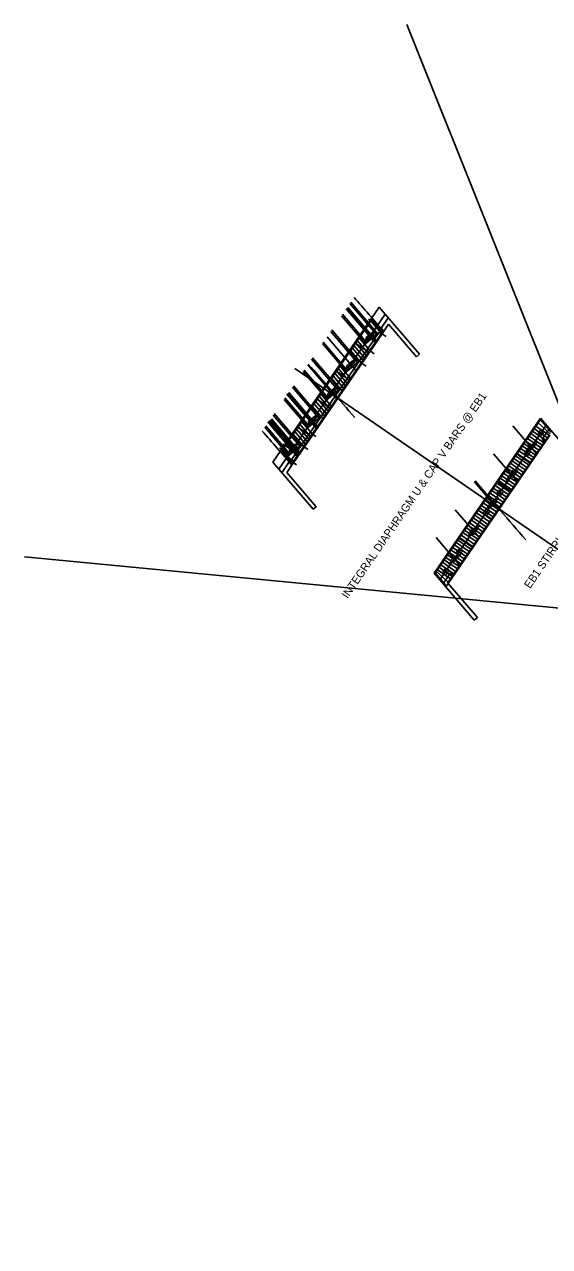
# Model space of a CAD drawing. Extents: x 2378999 to 2381348, y 331302 to 333122.
# Drawn here: x 2378998.8 to 2379130.1, y 331301.9 to 331607.3 of the extents above; entities that cross this region are included whole.
import ezdxf

# ---------------------------------------------------------------- set-up
doc = ezdxf.new("R2010")
doc.units = 0
for name, color, linetype in [('Dimension Lines', 7, 'Continuous'), ('Dimension Lines CELL', 7, 'Continuous'), ('Mis Work Point CELL', 7, 'Continuous'), ('P_SMU_Approach_Slab', 7, 'Continuous'), ('P_SMU_Bent_Cap', 7, 'Continuous'), ('P_SMU_Concrete_Barrier_Rail', 7, 'Continuous'), ('P_SMU_D_Deck_Outline', 7, 'Continuous'), ('P_SMU_Deck', 7, 'Continuous'), ('P_SMU_Girder_Concrete', 7, 'Continuous'), ('P_SMU_Mis_L_Lines', 7, 'Continuous'), ('P_SMU_Mis_Long_Chord', 7, 'Continuous'), ('P_SMU_Mis_Short_Chord', 7, 'Continuous'), ('P_SMU_Rebar_B_Bar', 7, 'Continuous'), ('P_SMU_Rebar_U_Bar', 7, 'Continuous'), ('Plan Sheet CELL', 7, 'Continuous'), ('Rebar Lines', 7, 'Continuous'), ('Scratch_Level_0', 7, 'Continuous'), ('Sup Concrete Slab Lines', 7, 'Continuous'), ('Text', 7, 'Continuous')]:
    doc.layers.add(name, color=color, linetype=linetype)

msp = doc.modelspace()

# ---------------------------------------------------------------- linework, layer by layer
at = {"layer": 'Dimension Lines'}
for p, q in [((2379216.61, 331301.94), (2379094.44, 331607.27)), ((2379085.41, 331533.22), (2379084.81, 331533.63)), ((2379088.1, 331530.07), (2379089.23, 331529.3)), ((2379085.15, 331525.79), (2379086.29, 331525.01)), ((2379083.03, 331522.7), (2379084.27, 331521.85)), ((2379129.98, 331504.63), (2379126.68, 331506.89)), ((2379127.26, 331507.73), (2379130.25, 331505.02)), ((2379127.83, 331508.56), (2379130.52, 331505.42)), ((2379127.86, 331501.54), (2379124.56, 331503.8)), ((2379128.28, 331502.16), (2379124.99, 331504.42)), ((2379128.71, 331502.77), (2379125.41, 331505.04)), ((2379129.13, 331503.39), (2379125.83, 331505.66)), ((2379063.28, 331501.01), (2379062.55, 331501.51)), ((2379126.58, 331499.68), (2379123.29, 331501.95)), ((2379127.01, 331500.3), (2379123.71, 331502.57)), ((2379127.43, 331500.92), (2379124.14, 331503.18)), ((2379065.97, 331497.86), (2379066.87, 331497.24)), ((2379124.04, 331495.97), (2379120.74, 331498.24)), ((2379124.46, 331496.59), (2379121.16, 331498.86)), ((2379124.88, 331497.21), (2379121.59, 331499.48)), ((2379125.31, 331497.83), (2379122.01, 331500.09)), ((2379125.73, 331498.45), (2379122.44, 331500.71)), ((2379121.91, 331492.88), (2379118.61, 331495.15)), ((2379122.34, 331493.5), (2379119.04, 331495.77)), ((2379123.19, 331494.74), (2379119.89, 331497)), ((2379123.61, 331495.36), (2379120.31, 331497.62)), ((2379119.79, 331489.79), (2379116.49, 331492.06)), ((2379120.21, 331490.41), (2379116.92, 331492.68)), ((2379120.64, 331491.03), (2379117.34, 331493.29)), ((2379121.06, 331491.65), (2379117.77, 331493.91)), ((2379121.49, 331492.27), (2379118.19, 331494.53)), ((2379117.66, 331486.7), (2379114.37, 331488.97)), ((2379118.09, 331487.32), (2379114.79, 331489.59)), ((2379118.51, 331487.94), (2379115.22, 331490.2)), ((2379118.94, 331488.56), (2379115.64, 331490.82)), ((2379115.54, 331483.61), (2379112.24, 331485.88)), ((2379116.39, 331484.85), (2379113.09, 331487.11)), ((2379116.82, 331485.47), (2379113.52, 331487.73)), ((2379117.24, 331486.08), (2379113.94, 331488.35)), ((2379113.42, 331480.52), (2379110.12, 331482.79)), ((2379113.84, 331481.14), (2379110.55, 331483.4)), ((2379114.27, 331481.76), (2379110.97, 331484.02)), ((2379114.69, 331482.37), (2379111.39, 331484.64)), ((2379115.12, 331482.99), (2379111.82, 331485.26)), ((2379111.29, 331477.43), (2379108, 331479.69)), ((2379111.72, 331478.05), (2379108.42, 331480.31)), ((2379112.14, 331478.67), (2379108.85, 331480.93)), ((2379112.99, 331479.9), (2379109.7, 331482.17)), ((2379109.6, 331474.96), (2379106.3, 331477.22)), ((2379110.02, 331475.58), (2379106.72, 331477.84)), ((2379110.44, 331476.19), (2379107.15, 331478.46)), ((2379110.87, 331476.81), (2379107.57, 331479.08)), ((2379303.66, 331445.13), (2378998.79, 331474.22)), ((2379107.05, 331471.25), (2379103.75, 331473.51)), ((2379107.47, 331471.87), (2379104.17, 331474.13)), ((2379107.9, 331472.48), (2379104.6, 331474.75)), ((2379108.32, 331473.1), (2379105.02, 331475.37)), ((2379108.75, 331473.72), (2379105.45, 331475.99)), ((2379101.51, 331470.25), (2379104.2, 331467.1)), ((2379101.78, 331470.65), (2379104.77, 331467.94)), ((2379105.35, 331468.78), (2379102.05, 331471.04)), ((2379106.2, 331470.01), (2379102.9, 331472.28)), ((2379106.62, 331470.63), (2379103.33, 331472.89))]:
    msp.add_line(p, q, dxfattribs=at)
at = {"layer": 'Dimension Lines CELL'}
msp.add_line((2379252.36, 331393.51), (2379066.4, 331521.27), dxfattribs=at)
at = {"layer": 'Mis Work Point CELL'}
for p, q in [((2379062.38, 331496.17), (2379089, 331534.91)), ((2379102.71, 331468.47), (2379129.32, 331507.2))]:
    msp.add_line(p, q, dxfattribs=at)
at = {"layer": 'P_SMU_Approach_Slab'}
msp.add_line((2379065.69, 331498.64), (2379087.52, 331530.4), dxfattribs=at)
for radius, start, end in [(7061.33, 221.090701, 221.097683), (7098.67, 221.168161, 221.175103)]:
    msp.add_arc((2384409.43, 336171.49), radius, start, end, dxfattribs=at)
at = {"layer": 'P_SMU_Bent_Cap'}
for p, q in [((2379086.66, 331530.6), (2379083.62, 331528)), ((2379081.87, 331523.63), (2379078.83, 331521.03)), ((2379077.09, 331516.66), (2379074.05, 331514.06)), ((2379072.3, 331509.69), (2379069.26, 331507.1)), ((2379067.51, 331502.73), (2379064.47, 331500.13)), ((2379126.99, 331502.89), (2379123.95, 331500.29)), ((2379122.2, 331495.92), (2379119.16, 331493.33)), ((2379117.41, 331488.96), (2379114.37, 331486.36)), ((2379112.63, 331481.99), (2379109.59, 331479.39)), ((2379107.84, 331475.02), (2379104.8, 331472.42))]:
    msp.add_line(p, q, dxfattribs=at)
at = {"layer": 'P_SMU_Concrete_Barrier_Rail'}
for radius, start, end in [(7060.38, 221.00405, 221.095684), (7099.63, 221.085985, 221.177079)]:
    msp.add_arc((2384409.43, 336171.49), radius, start, end, dxfattribs=at)
at = {"layer": 'P_SMU_D_Deck_Outline'}
for p, q in [((2379085.66, 331530.24), (2379084.14, 331528.94)), ((2379084.63, 331528.37), (2379084.14, 331528.94)), ((2379086.15, 331529.66), (2379084.63, 331528.37)), ((2379086.15, 331529.66), (2379085.66, 331530.24)), ((2379080.87, 331523.27), (2379079.35, 331521.97)), ((2379081.36, 331522.7), (2379079.84, 331521.4)), ((2379081.36, 331522.7), (2379080.87, 331523.27)), ((2379079.84, 331521.4), (2379079.35, 331521.97)), ((2379076.08, 331516.3), (2379074.56, 331515)), ((2379076.57, 331515.73), (2379076.08, 331516.3)), ((2379075.05, 331514.43), (2379074.56, 331515)), ((2379076.57, 331515.73), (2379075.05, 331514.43)), ((2379071.3, 331509.33), (2379069.78, 331508.03)), ((2379070.26, 331507.46), (2379069.78, 331508.03)), ((2379071.78, 331508.76), (2379070.26, 331507.46)), ((2379071.78, 331508.76), (2379071.3, 331509.33)), ((2379066.51, 331502.36), (2379064.99, 331501.06)), ((2379065.47, 331500.49), (2379064.99, 331501.06)), ((2379067, 331501.79), (2379065.47, 331500.49)), ((2379067, 331501.79), (2379066.51, 331502.36)), ((2379125.99, 331502.53), (2379124.47, 331501.23)), ((2379124.95, 331500.66), (2379124.47, 331501.23)), ((2379126.47, 331501.96), (2379124.95, 331500.66)), ((2379126.47, 331501.96), (2379125.99, 331502.53)), ((2379121.2, 331495.56), (2379119.68, 331494.26)), ((2379121.69, 331494.99), (2379120.16, 331493.69)), ((2379121.69, 331494.99), (2379121.2, 331495.56)), ((2379120.16, 331493.69), (2379119.68, 331494.26)), ((2379116.41, 331488.59), (2379114.89, 331487.29)), ((2379116.9, 331488.02), (2379116.41, 331488.59)), ((2379115.38, 331486.72), (2379114.89, 331487.29)), ((2379116.9, 331488.02), (2379115.38, 331486.72)), ((2379111.62, 331481.62), (2379110.1, 331480.32)), ((2379110.59, 331479.75), (2379110.1, 331480.32)), ((2379112.11, 331481.05), (2379110.59, 331479.75)), ((2379112.11, 331481.05), (2379111.62, 331481.62)), ((2379106.84, 331474.65), (2379105.31, 331473.36)), ((2379105.8, 331472.79), (2379105.31, 331473.36)), ((2379107.32, 331474.08), (2379105.8, 331472.79)), ((2379107.32, 331474.08), (2379106.84, 331474.65))]:
    msp.add_line(p, q, dxfattribs=at)
at = {"layer": 'P_SMU_Deck'}
for p, q in [((2379086.81, 331529.79), (2379080.17, 331537.55)), ((2379087.12, 331530.06), (2379080.42, 331537.91)), ((2379084.08, 331527.46), (2379078.07, 331534.49)), ((2379084.4, 331527.73), (2379078.32, 331534.85)), ((2379086.82, 331527.78), (2379079.47, 331536.39)), ((2379087.04, 331527.97), (2379079.69, 331536.58)), ((2379082.02, 331522.82), (2379075.39, 331530.58)), ((2379082.34, 331523.09), (2379075.63, 331530.94)), ((2379087.12, 331530.06), (2379084.08, 331527.46)), ((2379079.29, 331520.49), (2379073.29, 331527.53)), ((2379079.61, 331520.76), (2379073.53, 331527.88)), ((2379077.23, 331515.85), (2379070.6, 331523.62)), ((2379077.55, 331516.12), (2379070.84, 331523.97)), ((2379082.34, 331523.09), (2379079.29, 331520.49)), ((2379074.51, 331513.53), (2379068.5, 331520.56)), ((2379074.82, 331513.8), (2379068.74, 331520.91)), ((2379072.44, 331508.88), (2379065.81, 331516.65)), ((2379072.76, 331509.16), (2379066.06, 331517)), ((2379077.55, 331516.12), (2379074.51, 331513.53)), ((2379069.72, 331506.56), (2379063.71, 331513.59)), ((2379070.04, 331506.83), (2379063.95, 331513.94)), ((2379071.79, 331506.31), (2379064.44, 331514.92)), ((2379072.01, 331506.5), (2379064.66, 331515.11)), ((2379067.97, 331502.19), (2379061.27, 331510.03)), ((2379065.25, 331499.86), (2379059.17, 331506.98)), ((2379067, 331499.34), (2379059.65, 331507.95)), ((2379067.23, 331499.53), (2379059.87, 331508.14)), ((2379067.67, 331499.91), (2379060.32, 331508.52)), ((2379067.89, 331500.1), (2379060.54, 331508.71)), ((2379067.66, 331501.92), (2379061.02, 331509.68)), ((2379072.76, 331509.16), (2379069.72, 331506.56)), ((2379064.93, 331499.59), (2379058.92, 331506.62)), ((2379067.97, 331502.19), (2379064.93, 331499.59))]:
    msp.add_line(p, q, dxfattribs=at)
at = {"layer": 'P_SMU_Girder_Concrete'}
for p, q in [((2379127.22, 331505.01), (2379127.79, 331505.83)), ((2379127.5, 331505.42), (2379128.31, 331504.86)), ((2379128.03, 331504.45), (2379128.6, 331505.28)), ((2379123.82, 331500.06), (2379124.39, 331500.89)), ((2379124.1, 331500.48), (2379124.92, 331499.92)), ((2379124.63, 331499.51), (2379125.2, 331500.33)), ((2379120.42, 331495.12), (2379120.99, 331495.94)), ((2379120.71, 331495.53), (2379121.52, 331494.97)), ((2379121.23, 331494.56), (2379121.8, 331495.39)), ((2379117.03, 331490.17), (2379117.59, 331491)), ((2379117.31, 331490.59), (2379118.12, 331490.03)), ((2379117.84, 331489.62), (2379118.4, 331490.44)), ((2379113.63, 331485.23), (2379114.2, 331486.05)), ((2379113.91, 331485.64), (2379114.72, 331485.08)), ((2379114.44, 331484.67), (2379115.01, 331485.5)), ((2379110.23, 331480.28), (2379110.8, 331481.11)), ((2379110.51, 331480.7), (2379111.32, 331480.14)), ((2379111.04, 331479.73), (2379111.61, 331480.55)), ((2379106.83, 331475.34), (2379107.4, 331476.16)), ((2379107.12, 331475.75), (2379107.93, 331475.19)), ((2379107.64, 331474.78), (2379108.21, 331475.61)), ((2379103.44, 331470.39), (2379104, 331471.22)), ((2379103.72, 331470.8), (2379104.53, 331470.25)), ((2379104.25, 331469.84), (2379104.81, 331470.66))]:
    msp.add_line(p, q, dxfattribs=at)
at = {"layer": 'P_SMU_Mis_L_Lines'}
for p, q in [((2379086.6, 331527.6), (2379079.25, 331536.2)), ((2379081.81, 331520.63), (2379074.46, 331529.23)), ((2379077.02, 331513.66), (2379069.67, 331522.26)), ((2379072.24, 331506.69), (2379064.88, 331515.3)), ((2379067.45, 331499.72), (2379060.1, 331508.33)), ((2379126.93, 331499.89), (2379120.89, 331506.95)), ((2379122.14, 331492.92), (2379116.11, 331499.98)), ((2379117.35, 331485.95), (2379111.32, 331493.01)), ((2379112.56, 331478.98), (2379106.53, 331486.04)), ((2379107.78, 331472.01), (2379101.74, 331479.07))]:
    msp.add_line(p, q, dxfattribs=at)
at = {"layer": 'P_SMU_Mis_Long_Chord'}
for centre, start, end in [((2384409.43, 336171.49), 221.045135, 221.188495), ((2384449.76, 336143.78), 221.06156, 221.218654)]:
    msp.add_arc(centre, 7080, start, end, dxfattribs=at)
at = {"layer": 'P_SMU_Mis_Short_Chord'}
for p, q in [((2379070.79, 331504.88), (2379071.66, 331504.29)), ((2379068.67, 331501.79), (2379069.66, 331501.11))]:
    msp.add_line(p, q, dxfattribs=at)
at = {"layer": 'P_SMU_Rebar_B_Bar'}
for p, q in [((2379060.92, 331497.88), (2379087.54, 331536.62)), ((2379087.54, 331536.62), (2379097.58, 331524.87)), ((2379089.78, 331533.99), (2379087.96, 331531.35)), ((2379087.96, 331531.35), (2379088.64, 331530.57)), ((2379089.87, 331532.35), (2379088.08, 331529.76)), ((2379089.87, 331532.35), (2379096.82, 331524.22)), ((2379066.26, 331497.99), (2379088.08, 331529.76)), ((2379081.45, 331527.76), (2379085.02, 331525.3)), ((2379096.82, 331524.22), (2379097.58, 331524.87)), ((2379076.64, 331520.75), (2379080.21, 331518.3)), ((2379071.83, 331513.74), (2379075.4, 331511.29)), ((2379101.25, 331470.17), (2379127.87, 331508.91)), ((2379127.87, 331508.91), (2379137.9, 331497.16)), ((2379067.01, 331506.74), (2379070.58, 331504.28)), ((2379130.19, 331504.65), (2379104.75, 331467.61)), ((2379130.11, 331506.29), (2379128.29, 331503.64)), ((2379060.92, 331497.88), (2379070.96, 331486.13)), ((2379063.17, 331495.25), (2379065.02, 331497.95)), ((2379064.42, 331495.32), (2379066.26, 331497.99)), ((2379065.02, 331497.95), (2379065.7, 331497.17)), ((2379121.78, 331500.05), (2379125.35, 331497.6)), ((2379064.42, 331495.32), (2379071.72, 331486.78)), ((2379116.97, 331493.04), (2379120.54, 331490.59)), ((2379071.72, 331486.78), (2379070.96, 331486.13)), ((2379112.15, 331486.04), (2379115.72, 331483.58)), ((2379107.34, 331479.03), (2379110.91, 331476.58)), ((2379103.49, 331467.55), (2379105.35, 331470.25)), ((2379101.25, 331470.17), (2379111.29, 331458.42)), ((2379104.75, 331467.61), (2379104.17, 331466.76)), ((2379104.75, 331467.61), (2379112.05, 331459.07)), ((2379112.05, 331459.07), (2379111.29, 331458.42))]:
    msp.add_line(p, q, dxfattribs=at)
for points in [[(2379128.51, 331503.96), (2379128.29, 331503.64), (2379128.97, 331502.86), (2379129.19, 331503.18)], [(2379105.35, 331470.25), (2379106.03, 331469.47), (2379105.81, 331469.15), (2379105.13, 331469.93)]]:
    msp.add_lwpolyline(points, close=True, dxfattribs=at)
for radius, start, end in [(7060, 221.086523, 221.094902), (7060.38, 221.087305, 221.095684), (7099.63, 221.16875, 221.177079), (7100, 221.169523, 221.177852)]:
    msp.add_arc((2384449.76, 336143.78), radius, start, end, dxfattribs=at)
at = {"layer": 'P_SMU_Rebar_U_Bar'}
for p, q in [((2379088.1, 331530.07), (2379085.41, 331533.22)), ((2379088.32, 331530.4), (2379085.63, 331533.55)), ((2379084.73, 331525.17), (2379082.04, 331528.32)), ((2379085.15, 331525.79), (2379082.47, 331528.94)), ((2379083.03, 331522.7), (2379080.34, 331525.84)), ((2379083.46, 331523.31), (2379080.77, 331526.46)), ((2379083.88, 331523.93), (2379081.19, 331527.08)), ((2379084.31, 331524.55), (2379081.62, 331527.7)), ((2379078.67, 331516.35), (2379075.98, 331519.49)), ((2379079.09, 331516.96), (2379076.4, 331520.11)), ((2379079.52, 331517.58), (2379076.83, 331520.73)), ((2379079.94, 331518.2), (2379077.25, 331521.35)), ((2379080.37, 331518.82), (2379077.68, 331521.97)), ((2379078.24, 331515.73), (2379075.55, 331518.88)), ((2379074.31, 331510), (2379071.62, 331513.14)), ((2379074.73, 331510.61), (2379072.04, 331513.76)), ((2379075.15, 331511.23), (2379072.46, 331514.38)), ((2379075.58, 331511.85), (2379072.89, 331515)), ((2379073.46, 331508.76), (2379070.77, 331511.91)), ((2379073.88, 331509.38), (2379071.19, 331512.53)), ((2379070.37, 331504.26), (2379067.68, 331507.41)), ((2379070.79, 331504.88), (2379068.1, 331508.03)), ((2379068.67, 331501.79), (2379065.98, 331504.94)), ((2379069.09, 331502.41), (2379066.4, 331505.56)), ((2379069.52, 331503.03), (2379066.83, 331506.18)), ((2379069.94, 331503.65), (2379067.25, 331506.79)), ((2379065.97, 331497.86), (2379063.28, 331501.01)), ((2379067.45, 331499.72), (2379063.53, 331502.41)), ((2379065.74, 331497.53), (2379063.05, 331500.68))]:
    msp.add_line(p, q, dxfattribs=at)
at = {"layer": 'Plan Sheet CELL'}
for p, q in [((2379077.17, 331513.87), (2379071.14, 331520.93)), ((2379117.5, 331486.16), (2379111.47, 331493.22))]:
    msp.add_line(p, q, dxfattribs=at)
at = {"layer": 'Rebar Lines'}
for p, q in [((2379126.12, 331506.37), (2379129.69, 331503.92)), ((2379122.72, 331501.42), (2379126.3, 331498.97)), ((2379119.33, 331496.48), (2379122.9, 331494.03)), ((2379115.93, 331491.53), (2379119.5, 331489.08)), ((2379112.53, 331486.59), (2379116.1, 331484.14)), ((2379109.13, 331481.64), (2379112.71, 331479.19)), ((2379105.74, 331476.7), (2379109.31, 331474.24)), ((2379102.34, 331471.75), (2379105.91, 331469.3))]:
    msp.add_line(p, q, dxfattribs=at)
at = {"layer": 'Scratch_Level_0'}
for p, q in [((2379062.97, 331500.55), (2379085.72, 331533.67)), ((2379065.68, 331497.45), (2379088.43, 331530.56)), ((2379101.39, 331470.08), (2379128, 331508.81)), ((2379130.06, 331504.74), (2379104.61, 331467.71))]:
    msp.add_line(p, q, dxfattribs=at)
for radius, start, end in [(7060.54, 221.061118, 221.094635), (7099.46, 221.142026, 221.175347)]:
    msp.add_arc((2384409.43, 336171.49), radius, start, end, dxfattribs=at)
at = {"layer": 'Text'}
for p, q in [((2379075.7, 331515.56), (2379075.7, 331515.56)), ((2379116.03, 331487.85), (2379116.03, 331487.85))]:
    msp.add_line(p, q, dxfattribs=at)

# ---------------------------------------------------------------- texts
at = {"layer": 'Sup Concrete Slab Lines'}
for s, p in [('INTEGRAL DIAPHRAGM U & CAP V BARS @ EB1', (2379079.61, 331463.67)), ('EB1 STIRRUPS', (2379125.23, 331466.18))]:
    msp.add_text(s, height=2, rotation=55.5093, dxfattribs=at).set_placement(p)

doc.saveas('drawing.dxf')
